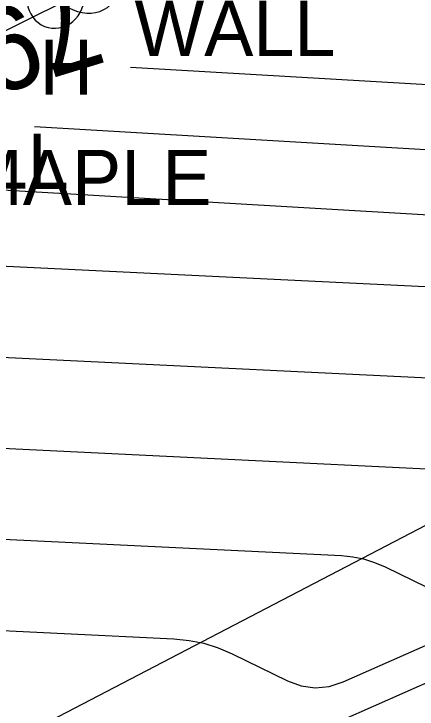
# Model space of a CAD drawing. Extents: x 1650836 to 1652450, y 332578 to 333908.
# Drawn here: x 1652099.77 to 1652114.39, y 332688.37 to 332713.58 of the extents above; entities that cross this region are included whole.
import ezdxf

# ---------------------------------------------------------------- set-up
doc = ezdxf.new("R2010")
doc.units = 0
for name, color, linetype in [('L_A', 7, 'Continuous'), ('L_C', 7, 'Continuous'), ('LELB', 7, 'Continuous'), ('LSOGCMA_T', 7, 'Continuous'), ('LSOGCMI', 7, 'Continuous'), ('LTD', 7, 'Continuous'), ('LW', 7, 'Continuous')]:
    doc.layers.add(name, color=color, linetype=linetype)

msp = doc.modelspace()

# ---------------------------------------------------------------- linework, layer by layer
at = {"layer": 'LELB'}
msp.add_lwpolyline([(1652048.756, 332662.461), (1652082.555, 332678.298), (1652130.366, 332703.201), (1652148.083, 332715.406), (1652159.47, 332726.367), (1652148.02, 332734.227), (1652128.413, 332739.339), (1652116.951, 332747.33), (1652106.793, 332756.875), (1652094.604, 332761.138), (1652083.802, 332764.466), (1652074.482, 332770.284), (1652065.17, 332770.428), (1652062.989, 332774.387), (1652054.537, 332784.724), (1652034.993, 332796.475), (1652025.062, 332801.1), (1652009.772, 332808.074), (1651988.967, 332816.401), (1651980.006, 332832.954), (1651960.575, 332843.477), (1651932.852, 332862.75), (1651890.753, 332886.019), (1651847.527, 332911.35)], dxfattribs=at)
at = {"layer": 'LSOGCMI'}
for points in [[(1652142.69, 332720.107), (1652133.618, 332720.391), (1652132.294, 332720.413), (1652130.97, 332720.394), (1652129.648, 332720.336), (1652128.327, 332720.238), (1652122.662, 332719.733), (1652121.634, 332719.509), (1652120.809, 332719.038), (1652120.188, 332718.32), (1652119.769, 332717.355), (1652118.5, 332713.002), (1652118.081, 332712.058), (1652117.458, 332711.402), (1652116.632, 332711.036), (1652115.602, 332710.958), (1652104.001, 332711.64)], [(1652145.955, 332715.903), (1652125.305, 332714.061), (1652124.63, 332713.914), (1652124.088, 332713.605), (1652123.68, 332713.133), (1652123.404, 332712.499), (1652122.571, 332709.639), (1652122.295, 332709.019), (1652121.886, 332708.589), (1652121.344, 332708.348), (1652120.667, 332708.297), (1652100.52, 332709.482)], [(1652125.732, 332705.635), (1652095.639, 332707.405)], [(1652129.849, 332702.945), (1652093.769, 332704.695)], [(1652123.779, 332699.938), (1652093.325, 332701.416)], [(1652114.748, 332692.778), (1652113.236, 332693.516), (1652112.853, 332693.68), (1652112.46, 332693.803), (1652112.055, 332693.885), (1652111.641, 332693.926), (1652091.36, 332694.91), (1652090.372, 332694.981), (1652089.391, 332695.097), (1652088.417, 332695.26), (1652087.449, 332695.468), (1652083.154, 332696.496), (1652082.411, 332696.685), (1652081.674, 332696.895), (1652080.943, 332697.125), (1652080.219, 332697.376), (1652077.334, 332698.421), (1652076.607, 332698.652), (1652075.869, 332698.824), (1652075.119, 332698.937), (1652074.358, 332698.99), (1652070.244, 332699.115)], [(1652117.71, 332696.932), (1652092.881, 332698.137)], [(1652069.596, 332697.692), (1652080.331, 332693.804), (1652081.086, 332693.542), (1652081.848, 332693.302), (1652082.616, 332693.083), (1652083.39, 332692.886), (1652086.501, 332692.142), (1652087.282, 332691.974), (1652088.067, 332691.843), (1652088.858, 332691.749), (1652089.654, 332691.692), (1652105.571, 332690.92), (1652106.121, 332690.865), (1652106.656, 332690.757), (1652107.177, 332690.594), (1652107.684, 332690.377), (1652109.685, 332689.4), (1652110.187, 332689.214), (1652110.69, 332689.146), (1652111.196, 332689.195), (1652111.705, 332689.361), (1652129.142, 332697.063)], [(1652111.658, 332687.97), (1652119.696, 332691.521), (1652119.916, 332691.597), (1652120.139, 332691.63), (1652120.364, 332691.622), (1652120.591, 332691.572), (1652121.833, 332691.184), (1652121.897, 332691.165), (1652121.961, 332691.148), (1652122.026, 332691.133), (1652122.092, 332691.119), (1652123.51, 332690.856), (1652123.522, 332690.853), (1652123.533, 332690.849), (1652123.543, 332690.843), (1652123.552, 332690.835), (1652129.42, 332685.378)]]:
    msp.add_lwpolyline(points, dxfattribs=at)
at = {"layer": 'LTD'}
for centre, major_axis, ratio in [((1652102.275, 332714.814), (-1.09, 0.792), 0.841452), ((1652101.275, 332714.147), (0.265, 1.061), 0.942809)]:
    msp.add_ellipse(centre, major_axis=major_axis, ratio=ratio, start_param=1.570796, end_param=4.712389, dxfattribs=at)
at = {"layer": 'LW'}
msp.add_lwpolyline([(1652113.729, 332729.971), (1652107.656, 332717.052), (1652097.986, 332712.237), (1652094.942, 332714.723), (1652087.881, 332709.509), (1652086.261, 332705.252), (1652079.661, 332707.671), (1652073.141, 332708.362), (1652066.208, 332710.013)], dxfattribs=at)

# ---------------------------------------------------------------- texts
at = {"layer": 'L_A'}
for s, p in [('WALL', (1652104.144, 332712.052)), ('H', (1652100.708, 332710.647)), ('WALL', (1652094.474, 332707.237))]:
    msp.add_text(s, height=2, dxfattribs=at).set_placement(p)
at = {"layer": 'L_C'}
msp.add_text('S.MAPLE', height=2, dxfattribs=at).set_placement((1652095.338, 332706.647))
at = {"layer": 'LSOGCMA_T'}
msp.add_text('795', height=3, rotation=197.0503, dxfattribs=at).set_placement((1652102.344, 332714.748))

doc.saveas('drawing.dxf')
